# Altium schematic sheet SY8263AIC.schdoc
size 127 x 101 mm
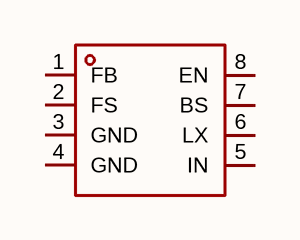
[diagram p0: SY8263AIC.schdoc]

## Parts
U?  sy8263aic  [TSOT-23-8_L2.9-W1.6-P0.65-LS2.8-BL]  (value not drawn)

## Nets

Not connected (* = marked no-connect by the designer): U? 1(FB) 2(FS) 3(GND) 4(GND) 5(IN) 6(LX) 7(BS) 8(EN)

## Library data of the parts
U? = sy8263aic: 功能类型:降压型;工作电压:4.5V~30V;输出电压:-;输出电流:3A;输出类型:可调;; Manufacturer: Silergy(矽力杰); AddInBom: yes; ModelId: dee2381274cf43f7a1d90e9872eb6b7d; ModelName: TSOT-23-8_L2.9-W1.6-H1.1-LS2.8-P0.65; ModelTransform: 110.45568,114.173,0,90,0,0,0,0,0; Function: 降压型; Output Current: 3A; Frequency - Switching: 500kHz~2.5MHz; Synchronous Rectifier: 是; Number of Outputs: 1; Topology: 降压式; Quiescent Current: 19uA; Switch tube (built-in/external): 内置; Output Type: 可调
